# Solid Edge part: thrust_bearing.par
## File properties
Title: Thrust bearing
Author: Abhinav Rai
Template: Normal.par
Last saved by: Rajat Kamboj
Revision: 16
Application: Solid Edge
Accuracy: 0.99
Material: aluminum
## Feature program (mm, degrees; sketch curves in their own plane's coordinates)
sketch for "unnamed RevolvedProtrusion 1" plane through (0, 0, 0) normal (0, -1, 0) x-axis (1, 0, 0)
  line (47.625, 16.8036) -> (66.929, 16.8036)
  line (66.929, 16.8036) -> (73.025, 10.7076)
  line (73.025, 10.7076) -> (73.025, -12.0254)
  line (73.025, -12.0254) -> (66.929, -18.1214)
  line (66.929, -18.1214) -> (47.625, -18.1214)
  line (47.625, -18.1214) -> (47.625, -7.1994)
  line (61.5714, -7.1994) -> (47.625, -7.1994)
  line (61.5714, 5.8816) -> (61.5714, -7.1994)
  line (47.625, 5.8816) -> (61.5714, 5.8816)
  line (47.625, 5.8816) -> (47.625, 16.8036)
revolve "unnamed RevolvedProtrusion 1" add finite 360 deg
sketch for "unnamed RevolvedProtrusion 2" plane through (0, 0, 0) normal (1, 0, 0) x-axis (0, 1, 0)
  line (69.977, 13.7556) -> (73.0652, 13.7556)
  line (73.0652, 13.7556) -> (74.6125, 12.2083)
  line (74.6125, 12.2083) -> (74.6125, -13.4669)
  line (74.6125, -13.4669) -> (73.006, -15.0734)
  line (73.006, -15.0734) -> (69.977, -15.0734)
revolve "unnamed RevolvedProtrusion 2" add full turn 360 deg
sketch for "unnamed RevolvedProtrusion 3" plane through (0, 0, 0) normal (0, -1, 0) x-axis (1, 0, 0)
revolve "unnamed RevolvedProtrusion 3" add full turn 360 deg about sketch line (-54.9674, 10.1232) -> (-54.9674, -18.1214)
pattern "unnamed Pattern 1" of "unnamed RevolvedProtrusion 3"
pattern "unnamed Pattern 2"
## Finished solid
Body 1: solid body, 39 faces, 39 edges, 25 vertices.
  Faces by surface: torus 25, plane 6, cone 4, cylinder 4
  Edges by curve: circle 39
Bounding box of the edges (mm; curved faces can reach further): 149.225 x 149.225 x 34.925, from (-74.6125, -74.6125, -18.1214) to (74.6125, 74.6125, 16.8036).
Cylindrical faces by radius (mm): R47.625 x2, R61.5714 x1, R74.6125 x1
Conical faces (half-angle, radius in mm at the cone's reference point): 45 deg R66.929 x1, 45 deg R73.025 x1, 45 deg R73.0652 x1, 45 deg R74.6125 x1
Toroidal faces (ring radius, tube radius in mm): R-0.1023 r6.604 x25
Planar faces by outward normal: +z 3, -z 3
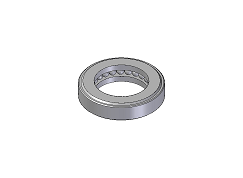
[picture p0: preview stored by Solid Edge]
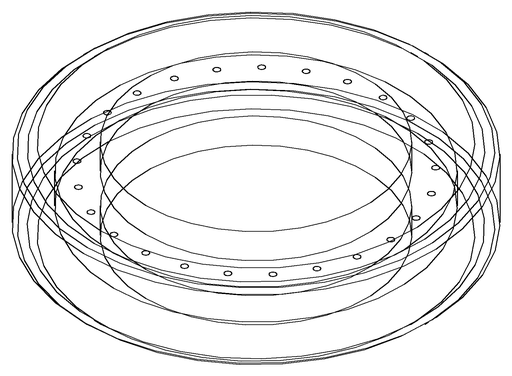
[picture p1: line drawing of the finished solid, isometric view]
